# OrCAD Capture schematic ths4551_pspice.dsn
size A
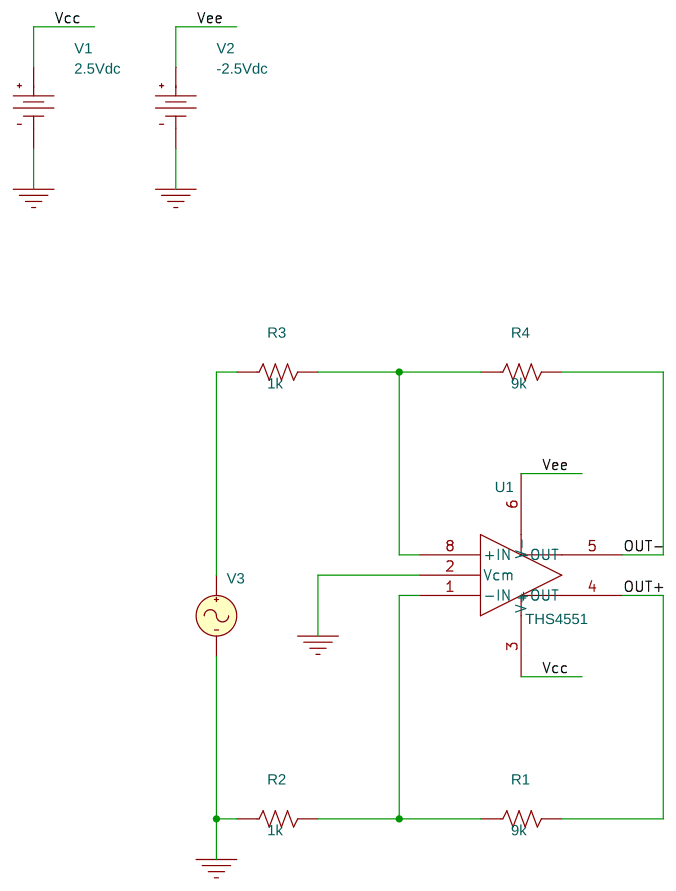
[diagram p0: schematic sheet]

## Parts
R1  9k  [AX/RC05]
R2  1k  [AX/RC05]
R3  1k  [AX/RC05]
R4  9k  [AX/RC05]
U1  THS4551
V1  VDC
V2  VDC
V3  VAC

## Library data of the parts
R1-R4 = R
U1 = THS4551
V1 = VDC: DC: 2.5Vdc
V2 = VDC: DC: -2.5Vdc
V3 = VAC

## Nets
Vcc: U1.3(V+) V1.0(+)
Vee: U1.6(V-) V2.0(+)
0: R2.1 U1.2(Vcm) V1.1(-) V2.1(-) V3.2(-)
OUT+: R1.2 U1.4(+OUT)
OUT-: R4.2 U1.5(-OUT)
N02463: R1.1 R2.2 U1.1(-IN)
N02936: R3.1 V3.1(+)
N02946: R3.2 R4.1 U1.8(+IN)
